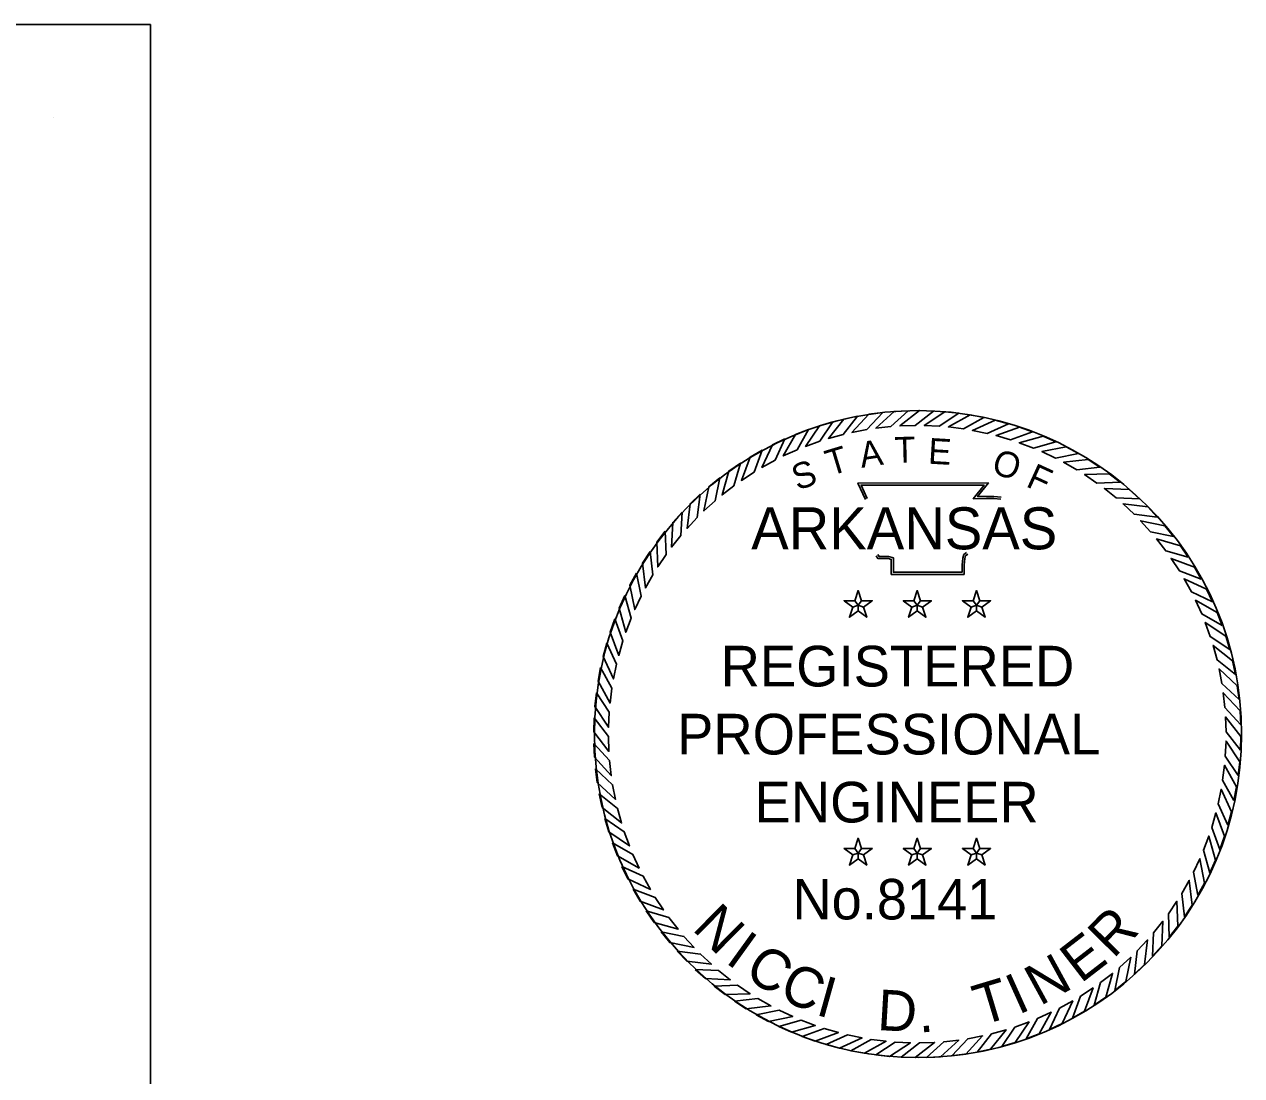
# Model space of a CAD drawing. Extents: x 0 to 38, y -1.3 to 22.5.
# Drawn here: x 33.533 to 38.047, y 18.1 to 22 of the extents above; entities that cross this region are included whole.
import ezdxf

# ---------------------------------------------------------------- set-up
doc = ezdxf.new("R2010")
doc.units = 0
for name, color, linetype in [('G-ANNO-STMP', 7, 'Continuous'), ('G-ANNO-TEXT', 7, 'Continuous'), ('G-Border-Paper', 7, 'Continuous'), ('G-No Plot-Stamp-1', 7, 'Continuous'), ('G-No Plot-Stamp-2', 7, 'Continuous')]:
    doc.layers.add(name, color=color, linetype=linetype)

msp = doc.modelspace()

# ---------------------------------------------------------------- linework, layer by layer
at = {"layer": 'G-ANNO-STMP'}
for points in [[(36.6223, 20.5464), (36.5718, 20.5358), (36.5146, 20.4638), (36.5684, 20.4786)], [(36.7156, 20.5602), (36.6644, 20.5536), (36.6017, 20.4863), (36.6564, 20.4967)], [(36.8096, 20.5666), (36.758, 20.564), (36.6902, 20.5018), (36.7456, 20.508)], [(36.9038, 20.5656), (36.8522, 20.567), (36.7797, 20.5104), (36.8355, 20.5122)], [(36.9976, 20.5572), (36.9463, 20.5627), (36.8696, 20.5119), (36.9253, 20.5093)], [(37.0905, 20.5414), (37.0398, 20.5509), (36.9594, 20.5064), (37.0147, 20.4994)], [(36.4406, 20.4973), (36.3924, 20.4789), (36.3471, 20.3988), (36.3979, 20.4218)], [(36.5305, 20.5254), (36.481, 20.5109), (36.4296, 20.4346), (36.482, 20.4535)], [(37.1819, 20.5185), (37.1321, 20.5319), (37.0484, 20.4938), (37.103, 20.4825)], [(37.2712, 20.4884), (37.2226, 20.5057), (37.1362, 20.4743), (37.1897, 20.4587)], [(36.3531, 20.4621), (36.3065, 20.44), (36.2676, 20.3567), (36.3165, 20.3835)], [(37.3579, 20.4514), (37.3108, 20.4725), (37.2222, 20.4479), (37.2743, 20.4282)], [(36.2687, 20.4203), (36.224, 20.3946), (36.1918, 20.3084), (36.2384, 20.339)], [(37.4414, 20.4077), (37.3961, 20.4324), (37.3058, 20.4149), (37.3563, 20.3912)], [(36.1879, 20.3719), (36.1453, 20.3427), (36.1199, 20.2543), (36.164, 20.2885)], [(37.5212, 20.3576), (37.478, 20.3858), (37.3866, 20.3754), (37.435, 20.3478)], [(36.1111, 20.3173), (36.0709, 20.2849), (36.0525, 20.1948), (36.0938, 20.2323)], [(37.5968, 20.3014), (37.556, 20.3329), (37.464, 20.3297), (37.5102, 20.2984)], [(37.6678, 20.2395), (37.6295, 20.2741), (37.5377, 20.2781), (37.5812, 20.2433)], [(36.0388, 20.2569), (36.0012, 20.2215), (35.99, 20.1302), (36.0282, 20.1708)], [(35.9714, 20.191), (35.9368, 20.1527), (35.9328, 20.0608), (35.9676, 20.1043)], [(37.7337, 20.1721), (37.6983, 20.2097), (37.607, 20.2209), (37.6477, 20.1827)], [(37.7942, 20.0998), (37.7618, 20.14), (37.6716, 20.1584), (37.7092, 20.1171)], [(35.9095, 20.12), (35.878, 20.0791), (35.8812, 19.9872), (35.9125, 20.0333)], [(37.8487, 20.023), (37.8196, 20.0656), (37.7312, 20.091), (37.7654, 20.0469)], [(35.8533, 20.0444), (35.8251, 20.0011), (35.8355, 19.9097), (35.8631, 19.9582)], [(37.8971, 19.9422), (37.8714, 19.9869), (37.7852, 20.0191), (37.8159, 19.9725)], [(35.8032, 19.9645), (35.7785, 19.9192), (35.796, 19.829), (35.8197, 19.8794)], [(37.939, 19.8578), (37.9169, 19.9044), (37.8335, 19.9433), (37.8604, 19.8944)], [(35.7595, 19.881), (35.7384, 19.834), (35.763, 19.7453), (35.7827, 19.7975)], [(36.6244, 19.8449), (36.6368, 19.8618), (36.6244, 19.8997), (36.6121, 19.8618)], [(36.8439, 19.8449), (36.8562, 19.8618), (36.8439, 19.8997), (36.8316, 19.8618)], [(37.0633, 19.8449), (37.0756, 19.8618), (37.0633, 19.8997), (37.051, 19.8618)], [(37.9741, 19.7703), (37.9557, 19.8185), (37.8757, 19.8638), (37.8986, 19.813)], [(36.6244, 19.8449), (36.6121, 19.8618), (36.5723, 19.8618), (36.6045, 19.8384)], [(36.6244, 19.8449), (36.6045, 19.8384), (36.5922, 19.8005), (36.6244, 19.8239)], [(36.6244, 19.8449), (36.6444, 19.8384), (36.6766, 19.8618), (36.6368, 19.8618)], [(36.6244, 19.8449), (36.6244, 19.8239), (36.6567, 19.8005), (36.6444, 19.8384)], [(36.8439, 19.8449), (36.8316, 19.8618), (36.7917, 19.8618), (36.8239, 19.8384)], [(36.8439, 19.8449), (36.8239, 19.8384), (36.8116, 19.8005), (36.8439, 19.8239)], [(36.8439, 19.8449), (36.8638, 19.8384), (36.896, 19.8618), (36.8562, 19.8618)], [(36.8439, 19.8449), (36.8439, 19.8239), (36.8761, 19.8005), (36.8638, 19.8384)], [(37.0633, 19.8449), (37.051, 19.8618), (37.0111, 19.8618), (37.0434, 19.8384)], [(37.0633, 19.8449), (37.0434, 19.8384), (37.0311, 19.8005), (37.0633, 19.8239)], [(37.0633, 19.8449), (37.0832, 19.8384), (37.1155, 19.8618), (37.0756, 19.8618)], [(37.0633, 19.8449), (37.0633, 19.8239), (37.0955, 19.8005), (37.0832, 19.8384)], [(35.7225, 19.7944), (35.7052, 19.7458), (35.7366, 19.6593), (35.7522, 19.7129)], [(38.0023, 19.6804), (37.9877, 19.7299), (37.9115, 19.7814), (37.9304, 19.7289)], [(35.6925, 19.7051), (35.679, 19.6553), (35.7171, 19.5716), (35.7284, 19.6262)], [(38.0233, 19.5886), (38.0127, 19.6391), (37.9407, 19.6963), (37.9554, 19.6425)], [(35.6695, 19.6137), (35.66, 19.563), (35.7045, 19.4825), (35.7115, 19.5379)], [(38.037, 19.4953), (38.0304, 19.5465), (37.9631, 19.6092), (37.9736, 19.5545)], [(35.6537, 19.5208), (35.6482, 19.4695), (35.699, 19.3928), (35.7016, 19.4485)], [(38.0434, 19.4013), (38.0408, 19.4529), (37.9787, 19.5207), (37.9848, 19.4653)], [(35.6453, 19.427), (35.6439, 19.3754), (35.7005, 19.3029), (35.6987, 19.3586)], [(38.0424, 19.3071), (38.0439, 19.3587), (37.9872, 19.4312), (37.989, 19.3754)], [(35.6443, 19.3327), (35.6469, 19.2812), (35.7091, 19.2134), (35.7029, 19.2688)], [(38.034, 19.2133), (38.0395, 19.2646), (37.9887, 19.3413), (37.9861, 19.2856)], [(35.6507, 19.2387), (35.6573, 19.1875), (35.7246, 19.1248), (35.7142, 19.1796)], [(38.0183, 19.1204), (38.0278, 19.1711), (37.9832, 19.2515), (37.9762, 19.1962)], [(35.6645, 19.1455), (35.6751, 19.095), (35.7471, 19.0378), (35.7323, 19.0915)], [(37.9953, 19.029), (38.0088, 19.0788), (37.9706, 19.1625), (37.9593, 19.1079)], [(35.6855, 19.0537), (35.7, 19.0041), (35.7763, 18.9527), (35.7574, 19.0052)], [(37.9652, 18.9397), (37.9826, 18.9883), (37.9511, 19.0747), (37.9356, 19.0212)], [(35.7136, 18.9637), (35.732, 18.9155), (35.8121, 18.8702), (35.7891, 18.921)], [(36.6244, 18.926), (36.6368, 18.943), (36.6244, 18.9809), (36.6121, 18.943)], [(36.8439, 18.926), (36.8562, 18.943), (36.8439, 18.9809), (36.8316, 18.943)], [(37.0633, 18.926), (37.0756, 18.943), (37.0633, 18.9809), (37.051, 18.943)], [(37.9282, 18.853), (37.9493, 18.9001), (37.9247, 18.9887), (37.9051, 18.9366)], [(36.6244, 18.926), (36.6121, 18.943), (36.5723, 18.943), (36.6045, 18.9195)], [(36.6244, 18.926), (36.6045, 18.9195), (36.5922, 18.8816), (36.6244, 18.9051)], [(36.6244, 18.926), (36.6444, 18.9195), (36.6766, 18.943), (36.6368, 18.943)], [(36.6244, 18.926), (36.6244, 18.9051), (36.6567, 18.8816), (36.6444, 18.9195)], [(36.8439, 18.926), (36.8316, 18.943), (36.7917, 18.943), (36.8239, 18.9195)], [(36.8439, 18.926), (36.8239, 18.9195), (36.8116, 18.8816), (36.8439, 18.9051)], [(36.8439, 18.926), (36.8638, 18.9195), (36.896, 18.943), (36.8562, 18.943)], [(36.8439, 18.926), (36.8439, 18.9051), (36.8761, 18.8816), (36.8638, 18.9195)], [(37.0633, 18.926), (37.051, 18.943), (37.0111, 18.943), (37.0434, 18.9195)], [(37.0633, 18.926), (37.0434, 18.9195), (37.0311, 18.8816), (37.0633, 18.9051)], [(37.0633, 18.926), (37.0832, 18.9195), (37.1155, 18.943), (37.0756, 18.943)], [(37.0633, 18.926), (37.0633, 18.9051), (37.0955, 18.8816), (37.0832, 18.9195)], [(35.7488, 18.8763), (35.7709, 18.8297), (35.8542, 18.7908), (35.8274, 18.8397)], [(37.8846, 18.7695), (37.9093, 18.8148), (37.8917, 18.9051), (37.868, 18.8547)], [(37.8345, 18.6897), (37.8627, 18.7329), (37.8523, 18.8243), (37.8247, 18.7759)], [(35.7907, 18.7919), (35.8164, 18.7471), (35.9025, 18.7149), (35.8719, 18.7615)], [(37.7783, 18.6141), (37.8098, 18.6549), (37.8066, 18.7469), (37.7753, 18.7007)], [(35.839, 18.711), (35.8682, 18.6684), (35.9566, 18.6431), (35.9224, 18.6871)], [(37.7163, 18.5431), (37.7509, 18.5814), (37.7549, 18.6732), (37.7201, 18.6297)], [(35.8936, 18.6342), (35.926, 18.594), (36.0161, 18.5757), (35.9786, 18.6169)], [(37.649, 18.4772), (37.6865, 18.5126), (37.6977, 18.6039), (37.6596, 18.5633)], [(35.954, 18.5619), (35.9895, 18.5244), (36.0807, 18.5132), (36.0401, 18.5513)], [(37.5767, 18.4167), (37.6169, 18.4491), (37.6352, 18.5393), (37.594, 18.5017)], [(36.0199, 18.4946), (36.0582, 18.46), (36.1501, 18.456), (36.1066, 18.4908)], [(37.4999, 18.3622), (37.5425, 18.3913), (37.5678, 18.4797), (37.5238, 18.4455)], [(36.0909, 18.4326), (36.1318, 18.4011), (36.2237, 18.4043), (36.1776, 18.4357)], [(37.419, 18.3138), (37.4638, 18.3395), (37.496, 18.4257), (37.4494, 18.395)], [(36.1666, 18.3764), (36.2098, 18.3482), (36.3012, 18.3586), (36.2527, 18.3862)], [(37.3346, 18.2719), (37.3812, 18.294), (37.4201, 18.3774), (37.3713, 18.3505)], [(36.2464, 18.3263), (36.2917, 18.3016), (36.3819, 18.3192), (36.3315, 18.3429)], [(37.2472, 18.2368), (37.2954, 18.2552), (37.3407, 18.3352), (37.2899, 18.3123)], [(36.3299, 18.2827), (36.377, 18.2616), (36.4656, 18.2862), (36.4134, 18.3058)], [(37.1572, 18.2086), (37.2068, 18.2232), (37.2582, 18.2994), (37.2057, 18.2805)], [(36.4165, 18.2457), (36.4651, 18.2283), (36.5516, 18.2598), (36.498, 18.2753)], [(36.5058, 18.2156), (36.5556, 18.2021), (36.6393, 18.2403), (36.5847, 18.2516)], [(36.9722, 18.1739), (37.0234, 18.1805), (37.0861, 18.2478), (37.0313, 18.2373)], [(37.0654, 18.1876), (37.1159, 18.1982), (37.1732, 18.2702), (37.1194, 18.2555)], [(36.5972, 18.1926), (36.6479, 18.1831), (36.7284, 18.2277), (36.673, 18.2347)], [(36.6901, 18.1769), (36.7414, 18.1714), (36.8181, 18.2222), (36.7624, 18.2248)], [(36.7839, 18.1685), (36.8355, 18.167), (36.908, 18.2237), (36.8523, 18.2219)], [(36.8782, 18.1675), (36.9297, 18.1701), (36.9975, 18.2322), (36.9421, 18.2261)]]:
    msp.add_lwpolyline(points, close=True, dxfattribs=at)
for points in [[(36.6516, 20.238), (36.6236, 20.2986), (37.1077, 20.2989), (37.0672, 20.248), (37.1001, 20.2485), (37.1276, 20.2488), (37.155, 20.2458)], [(36.6586, 20.2412), (36.6356, 20.2909), (37.0918, 20.2912), (37.0512, 20.2402), (37.1002, 20.2408), (37.1272, 20.2412), (37.1542, 20.2382)], [(37.0314, 20.0351), (37.0231, 20.0284), (37.0204, 20.0184), (37.0177, 19.9933), (37.0177, 19.9598), (36.7475, 19.9598), (36.7475, 20.005), (36.7475, 20.015), (36.7365, 20.0184), (36.6981, 20.0184), (36.6912, 20.0288)], [(37.0266, 20.0411), (37.0164, 20.0328), (37.0129, 20.0198), (37.01, 19.9937), (37.01, 19.9675), (36.7551, 19.9675), (36.7551, 20.005), (36.7551, 20.0207), (36.7377, 20.0261), (36.7022, 20.0261), (36.6977, 20.033)]]:
    msp.add_lwpolyline(points, dxfattribs=at)
at = {"layer": 'G-ANNO-TEXT'}
msp.add_line((33.6421, 21.6538), (33.6421, 21.6538), dxfattribs=at)
at = {"layer": 'G-Border-Paper'}
msp.add_lwpolyline([(34, 22), (0, 22), (0, 0), (34, 0)], close=True, dxfattribs=at)
at = {"layer": 'G-No Plot-Stamp-1'}
msp.add_circle((36.8467, 19.367), 1.2, dxfattribs=at)
at = {"layer": 'G-No Plot-Stamp-2'}
msp.add_circle((36.8467, 19.367), 1.2, dxfattribs=at)

# ---------------------------------------------------------------- texts
at = {"layer": 'G-ANNO-STMP'}
for s, height, rotation, p in [('A', 0.0955, 8.6788, (36.6369, 20.3545)), ('T', 0.0955, 1.4789, (36.7602, 20.3735)), ('E', 0.0955, 356.672, (36.8824, 20.3706)), ('T', 0.0955, 16.9015, (36.5209, 20.3242)), ('O', 0.0955, 341.2218, (37.1142, 20.3379)), ('S', 0.0955, 19.7726, (36.3995, 20.2697)), ('F', 0.0955, 335.3628, (37.2429, 20.2875)), ('N', 0.1509, 315.2676, (36.0055, 18.6433)), ('R', 0.1509, 45.478, (37.5707, 18.5313)), ('I', 0.1509, 324.2141, (36.1283, 18.5217)), ('E', 0.1509, 37.6498, (37.4501, 18.4401)), ('C', 0.1509, 328.6873, (36.1964, 18.4685)), ('C', 0.1509, 336.5155, (36.3248, 18.3887)), ('N', 0.1509, 28.7033, (37.2986, 18.3571)), ('I', 0.1509, 344.3437, (36.4629, 18.3271)), ('T', 0.1509, 16.7747, (37.08, 18.285)), ('I', 0.1509, 24.2301, (37.2184, 18.3248)), ('D', 0.1509, 356.6451, (36.6932, 18.2698)), ('.', 0.1509, 4.846, (36.8513, 18.2595))]:
    msp.add_text(s, height=height, rotation=rotation, dxfattribs=at).set_placement(p)
for s, height, p in [('ARKANSAS', 0.15583, (36.228, 20.0526)), ('REGISTERED', 0.15086, (36.1147, 19.5439)), ('PROFESSIONAL', 0.15086, (35.9531, 19.2916)), ('ENGINEER', 0.15086, (36.2404, 19.0393)), ('No.8141', 0.15026, (36.3811, 18.6797))]:
    msp.add_text(s, height=height, dxfattribs=at).set_placement(p)

doc.saveas('drawing.dxf')
